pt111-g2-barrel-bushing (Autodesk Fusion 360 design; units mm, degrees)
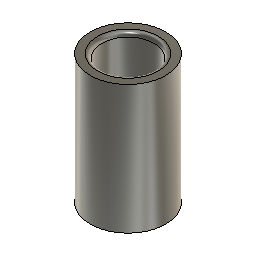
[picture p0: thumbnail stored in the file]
sketch "Sketch1" plane through (0, 0, 0) normal (0, 0, 1) x axis (1, 0, 0)
  circle C1 centre (10, 10) radius 2.3
  circle C2 centre (10, 10) radius 1.59
  concentric C1 C2
  dimension "d1" diameter C1 = 4.6
  dimension "d2" diameter C2 = 3.18
extrude "Extrude1" new body sketch "Sketch1" along normal blind 7.85
fillet "Fillet1" radius 0.25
